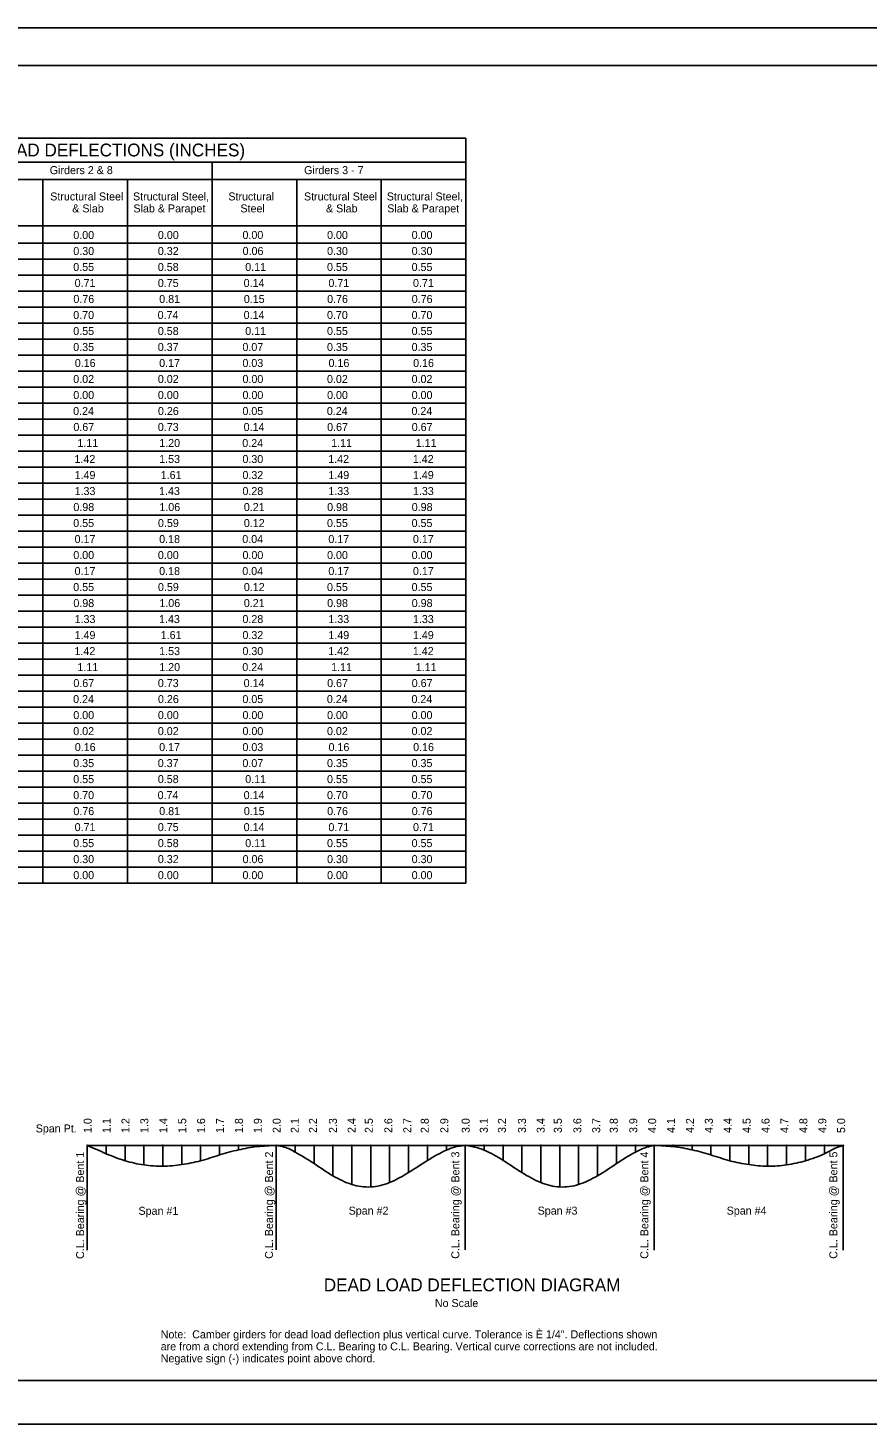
# Model space of a CAD drawing. Extents: x 208.7 to 242.8, y 328.9 to 350.7.
# Drawn here: x 217.57 to 230.69, y 328.91 to 350.71 of the extents above; entities that cross this region are included whole.
import ezdxf

# ---------------------------------------------------------------- set-up
doc = ezdxf.new("R2010")
doc.units = 0
for name, color, linetype in [('border', 7, 'Continuous'), ('Border 2660-Hwy18 - Level 62', 7, 'Continuous'), ('Dimensions', 7, 'Continuous'), ('Level 20', 7, 'Continuous'), ('Level 25', 7, 'Continuous'), ('Level 40', 7, 'Continuous'), ('Level 41', 7, 'Continuous'), ('Steel', 7, 'Continuous'), ('Text', 7, 'Continuous'), ('Title Text', 7, 'Continuous')]:
    doc.layers.add(name, color=color, linetype=linetype)

msp = doc.modelspace()

# ---------------------------------------------------------------- linework, layer by layer
at = {"layer": 'border'}
for p, q in [((210.28, 350.129), (242.291, 350.129)), ((242.291, 329.584), (210.28, 329.584))]:
    msp.add_line(p, q, dxfattribs=at)
at = {"layer": 'Border 2660-Hwy18 - Level 62'}
msp.add_lwpolyline([(208.659, 350.715), (242.778, 350.715), (242.778, 328.905), (208.659, 328.905)], close=True, dxfattribs=at)
at = {"layer": 'Dimensions'}
for centre in [(218.498, 333.259), (218.793, 333.259), (219.088, 333.259), (219.384, 333.259), (219.679, 333.259), (219.975, 333.259), (220.27, 333.259), (220.565, 333.259), (220.861, 333.259), (221.156, 333.259), (221.452, 333.259), (221.747, 333.259), (222.042, 333.259), (222.338, 333.259), (222.633, 333.259), (222.929, 333.259), (223.224, 333.259), (223.519, 333.259), (223.815, 333.259), (224.11, 333.259), (224.406, 333.259), (224.701, 333.259), (224.996, 333.259), (225.292, 333.259), (225.587, 333.259), (225.883, 333.259), (226.178, 333.259), (226.473, 333.259), (226.769, 333.259), (227.064, 333.259), (227.36, 333.259), (227.655, 333.259), (227.951, 333.259), (228.246, 333.259), (228.541, 333.259), (228.837, 333.259), (229.132, 333.259), (229.428, 333.259), (229.723, 333.259), (230.018, 333.259), (230.314, 333.259)]:
    msp.add_circle(centre, 0.004, dxfattribs=at)
at = {"layer": 'Level 20'}
for p, q in [((218.498, 331.622), (218.498, 333.259)), ((221.452, 331.626), (221.452, 333.259)), ((224.406, 331.626), (224.406, 333.259)), ((227.36, 331.774), (227.36, 333.259)), ((227.36, 331.623), (227.36, 333.259)), ((230.314, 331.774), (230.314, 333.259)), ((230.314, 331.622), (230.314, 333.259))]:
    msp.add_line(p, q, dxfattribs=at)
at = {"layer": 'Level 25'}
for p, q in [((218.498, 333.259), (221.452, 333.259)), ((224.406, 333.259), (221.452, 333.259)), ((230.314, 333.259), (224.406, 333.259))]:
    msp.add_line(p, q, dxfattribs=at)
at = {"layer": 'Level 41'}
for p, q in [((218.793, 333.259), (218.793, 333.129)), ((219.088, 333.259), (219.088, 333.019)), ((219.384, 333.259), (219.384, 332.954)), ((219.679, 333.259), (219.679, 332.934)), ((219.975, 333.259), (219.975, 332.959)), ((220.27, 333.259), (220.27, 333.019)), ((220.565, 333.259), (220.565, 333.109)), ((220.861, 333.259), (220.861, 333.189)), ((221.156, 333.259), (221.156, 333.239)), ((221.747, 333.259), (221.747, 333.154)), ((222.042, 333.259), (222.042, 332.974)), ((222.338, 333.259), (222.338, 332.784)), ((222.633, 333.259), (222.633, 332.649)), ((222.929, 333.259), (222.929, 332.609)), ((223.224, 333.259), (223.224, 332.679)), ((223.519, 333.259), (223.519, 332.834)), ((223.815, 333.259), (223.815, 333.024)), ((224.11, 333.259), (224.11, 333.184)), ((224.701, 333.259), (224.701, 333.184)), ((224.996, 333.259), (224.996, 333.024)), ((225.292, 333.259), (225.292, 332.834)), ((225.587, 333.259), (225.587, 332.679)), ((225.883, 333.259), (225.883, 332.609)), ((226.178, 333.259), (226.178, 332.649)), ((226.473, 333.259), (226.473, 332.784)), ((226.769, 333.259), (226.769, 332.974)), ((227.064, 333.259), (227.064, 333.154)), ((227.655, 333.259), (227.655, 333.239)), ((227.951, 333.259), (227.951, 333.189)), ((228.246, 333.259), (228.246, 333.109)), ((228.541, 333.259), (228.541, 333.019)), ((228.837, 333.259), (228.837, 332.959)), ((229.132, 333.259), (229.132, 332.934)), ((229.428, 333.259), (229.428, 332.954)), ((229.723, 333.259), (229.723, 333.019)), ((230.018, 333.259), (230.018, 333.129))]:
    msp.add_line(p, q, dxfattribs=at)
for points in [[(218.498, 333.259), (218.793, 333.129), (219.088, 333.019), (219.384, 332.954), (219.679, 332.934), (219.975, 332.959), (220.27, 333.019), (220.565, 333.109), (220.861, 333.189), (221.156, 333.239), (221.452, 333.259)], [(221.452, 333.259), (221.577, 333.233), (221.747, 333.154), (222.042, 332.974), (222.338, 332.784), (222.633, 332.649), (222.929, 332.609), (223.224, 332.679), (223.519, 332.834), (223.815, 333.024), (224.11, 333.184), (224.235, 333.229), (224.406, 333.259)], [(224.406, 333.259), (224.501, 333.244), (224.701, 333.184), (224.996, 333.024), (225.292, 332.834), (225.587, 332.679), (225.883, 332.609), (226.178, 332.649), (226.473, 332.784), (226.769, 332.974), (227.064, 333.154), (227.24, 333.229), (227.36, 333.259)], [(227.36, 333.259), (227.655, 333.239), (227.951, 333.189), (228.246, 333.109), (228.541, 333.019), (228.837, 332.959), (229.132, 332.934), (229.428, 332.954), (229.723, 333.019), (230.018, 333.129), (230.177, 333.21), (230.314, 333.259)]]:
    msp.add_spline(points, degree=3, dxfattribs=at)
at = {"layer": 'Steel'}
for p, q in [((224.415, 348.995), (210.932, 348.995)), ((224.415, 348.995), (224.415, 337.354)), ((224.415, 348.618), (210.932, 348.618)), ((220.449, 348.618), (220.449, 337.354)), ((224.415, 348.349), (212.517, 348.349)), ((217.805, 348.349), (217.805, 337.354)), ((219.127, 348.349), (219.127, 337.354)), ((221.771, 348.349), (221.771, 337.354)), ((223.093, 348.349), (223.093, 337.354)), ((224.415, 347.623), (210.932, 347.623)), ((224.415, 347.354), (211.725, 347.354)), ((224.415, 347.104), (211.725, 347.104)), ((224.415, 346.854), (211.725, 346.854)), ((224.415, 346.604), (211.725, 346.604)), ((224.415, 346.354), (211.725, 346.354)), ((224.415, 346.104), (211.725, 346.104)), ((224.415, 345.854), (211.725, 345.854)), ((224.415, 345.604), (211.725, 345.604)), ((224.415, 345.354), (211.725, 345.354)), ((224.415, 345.104), (211.725, 345.104)), ((224.415, 344.854), (211.725, 344.854)), ((224.415, 344.604), (211.725, 344.604)), ((224.415, 344.354), (211.725, 344.354)), ((224.415, 344.104), (211.725, 344.104)), ((224.415, 343.854), (211.725, 343.854)), ((224.415, 343.604), (211.725, 343.604)), ((224.415, 343.354), (211.725, 343.354)), ((224.415, 343.104), (211.725, 343.104)), ((224.415, 342.854), (211.725, 342.854)), ((224.415, 342.604), (211.725, 342.604)), ((224.415, 342.354), (211.725, 342.354)), ((224.415, 342.104), (211.725, 342.104)), ((224.415, 341.854), (211.725, 341.854)), ((224.415, 341.604), (211.725, 341.604)), ((224.415, 341.354), (211.725, 341.354)), ((224.415, 341.104), (211.725, 341.104)), ((224.415, 340.854), (211.725, 340.854)), ((224.415, 340.604), (211.725, 340.604)), ((224.415, 340.354), (211.725, 340.354)), ((224.415, 340.104), (211.725, 340.104)), ((224.415, 339.854), (211.725, 339.854)), ((224.415, 339.604), (211.725, 339.604)), ((224.415, 339.354), (211.725, 339.354)), ((224.415, 339.104), (211.725, 339.104)), ((224.415, 338.854), (211.725, 338.854)), ((224.415, 338.604), (211.725, 338.604)), ((224.415, 338.354), (211.725, 338.354)), ((224.415, 338.104), (211.725, 338.104)), ((224.415, 337.854), (211.725, 337.854)), ((224.415, 337.604), (211.725, 337.604)), ((224.415, 337.354), (210.932, 337.354))]:
    msp.add_line(p, q, dxfattribs=at)

# ---------------------------------------------------------------- texts
at = {"layer": 'Level 40'}
for s, height, rotation, p in [('Span Pt.', 0.125, 359.9998, (217.692, 333.461)), ('1.0', 0.125, 89.9998, (218.567, 333.452)), ('1.1', 0.125, 89.9998, (218.863, 333.452)), ('1.2', 0.125, 89.9998, (219.158, 333.452)), ('1.3', 0.125, 89.9998, (219.453, 333.452)), ('1.4', 0.125, 89.9998, (219.749, 333.452)), ('1.5', 0.125, 89.9998, (220.044, 333.452)), ('1.6', 0.125, 89.9998, (220.34, 333.452)), ('1.7', 0.125, 89.9998, (220.635, 333.452)), ('1.8', 0.125, 89.9998, (220.93, 333.452)), ('1.9', 0.125, 89.9998, (221.226, 333.452)), ('2.0', 0.125, 89.9998, (221.521, 333.452)), ('2.1', 0.125, 89.9998, (221.804, 333.452)), ('2.2', 0.125, 89.9998, (222.087, 333.452)), ('2.3', 0.125, 89.9998, (222.4, 333.452)), ('2.4', 0.125, 89.9998, (222.693, 333.452)), ('2.5', 0.125, 89.9998, (222.961, 333.452)), ('2.6', 0.125, 89.9998, (223.266, 333.452)), ('2.7', 0.125, 89.9998, (223.561, 333.452)), ('2.8', 0.125, 89.9998, (223.835, 333.452)), ('2.9', 0.125, 89.9998, (224.14, 333.452)), ('3.0', 0.125, 89.9998, (224.475, 333.452)), ('3.1', 0.125, 89.9998, (224.758, 333.452)), ('3.2', 0.125, 89.9998, (225.041, 333.452)), ('3.3', 0.125, 89.9998, (225.354, 333.452)), ('3.4', 0.125, 89.9998, (225.647, 333.452)), ('3.5', 0.125, 89.9998, (225.915, 333.452)), ('3.6', 0.125, 89.9998, (226.22, 333.452)), ('3.7', 0.125, 89.9998, (226.515, 333.452)), ('3.8', 0.125, 89.9998, (226.789, 333.452)), ('3.9', 0.125, 89.9998, (227.094, 333.452)), ('4.0', 0.125, 89.9998, (227.389, 333.452)), ('4.1', 0.125, 89.9998, (227.684, 333.452)), ('4.2', 0.125, 89.9998, (227.98, 333.452)), ('4.3', 0.125, 89.9998, (228.275, 333.452)), ('4.4', 0.125, 89.9998, (228.571, 333.452)), ('4.5', 0.125, 89.9998, (228.866, 333.452)), ('4.6', 0.125, 89.9998, (229.161, 333.452)), ('4.7', 0.125, 89.9998, (229.457, 333.452)), ('4.8', 0.125, 89.9998, (229.752, 333.452)), ('4.9', 0.125, 89.9998, (230.048, 333.452)), ('5.0', 0.125, 89.9998, (230.343, 333.452)), ('C.L. Bearing @ Bent 1', 0.12501, 89.9998, (218.448, 331.485)), ('C.L. Bearing @ Bent 2', 0.12501, 89.9998, (221.401, 331.487)), ('C.L. Bearing @ Bent 3', 0.12501, 89.9998, (224.313, 331.487)), ('C.L. Bearing @ Bent 4', 0.12501, 89.9998, (227.267, 331.487)), ('C.L. Bearing @ Bent 5', 0.12501, 89.9998, (230.221, 331.487)), ('Span #1 ', 0.125, 359.9998, (219.299, 332.174)), ('Span #2', 0.125, 359.9998, (222.583, 332.177)), ('Span #3', 0.125, 359.9998, (225.537, 332.177)), ('Span #4', 0.125, 359.9998, (228.491, 332.177))]:
    msp.add_text(s, height=height, rotation=rotation, dxfattribs=at).set_placement(p)
for s, p in [('No Scale', (223.931, 330.733)), ('Note:  Camber girders for dead load deflection plus vertical curve. Tolerance is È 1/4". Deflections shown', (219.646, 330.245)), ('are from a chord extending from C.L. Bearing to C.L. Bearing. Vertical curve corrections are not included.', (219.646, 330.057)), ('Negative sign (-) indicates point above chord.', (219.646, 329.87))]:
    msp.add_text(s, height=0.125, dxfattribs=at).set_placement(p)
at = {"layer": 'Level 41'}
msp.add_text(' DEAD LOAD DEFLECTION DIAGRAM ', height=0.2, dxfattribs=at).set_placement((222.12, 330.98))
at = {"layer": 'Text'}
for s, p in [('Girders 2 & 8', (217.912, 348.431)), ('Girders 3 - 7', (221.887, 348.431)), ('Structural Steel', (217.919, 348.02)), ('Structural Steel,', (219.213, 348.02)), ('Structural', (220.703, 348.02)), ('Structural Steel', (221.885, 348.02)), ('Structural Steel,', (223.179, 348.02)), ('& Slab', (218.263, 347.833)), ('Slab & Parapet', (219.22, 347.833)), ('Steel', (220.892, 347.833)), ('& Slab', (222.229, 347.833)), ('Slab & Parapet', (223.186, 347.833)), ('0.00', (218.28, 347.418)), ('0.00', (219.602, 347.418)), ('0.00', (220.924, 347.418)), ('0.00', (222.246, 347.418)), ('0.00', (223.568, 347.418)), ('0.30', (218.28, 347.168)), ('0.32', (219.601, 347.168)), ('0.06', (220.926, 347.168)), ('0.30', (222.246, 347.168)), ('0.30', (223.568, 347.168)), ('0.55', (218.279, 346.918)), ('0.58', (219.601, 346.918)), ('0.11', (220.967, 346.918)), ('0.55', (222.245, 346.918)), ('0.55', (223.567, 346.918)), ('0.71', (218.301, 346.668)), ('0.75', (219.601, 346.668)), ('0.14', (220.942, 346.668)), ('0.71', (222.267, 346.668)), ('0.71', (223.589, 346.668)), ('0.76', (218.281, 346.418)), ('0.81', (219.623, 346.418)), ('0.15', (220.945, 346.418)), ('0.76', (222.247, 346.418)), ('0.76', (223.569, 346.418)), ('0.70', (218.279, 346.168)), ('0.74', (219.598, 346.168)), ('0.14', (220.942, 346.168)), ('0.70', (222.245, 346.168)), ('0.70', (223.567, 346.168)), ('0.55', (218.279, 345.918)), ('0.58', (219.601, 345.918)), ('0.11', (220.967, 345.918)), ('0.55', (222.245, 345.918)), ('0.55', (223.567, 345.918)), ('0.35', (218.279, 345.668)), ('0.37', (219.6, 345.668)), ('0.07', (220.923, 345.668)), ('0.35', (222.245, 345.668)), ('0.35', (223.567, 345.668)), ('0.16', (218.303, 345.418)), ('0.17', (219.622, 345.418)), ('0.03', (220.923, 345.418)), ('0.16', (222.269, 345.418)), ('0.16', (223.591, 345.418)), ('0.02', (218.279, 345.168)), ('0.02', (219.601, 345.168)), ('0.00', (220.924, 345.168)), ('0.02', (222.245, 345.168)), ('0.02', (223.567, 345.168)), ('0.00', (218.28, 344.918)), ('0.00', (219.602, 344.918)), ('0.00', (220.924, 344.918)), ('0.00', (222.246, 344.918)), ('0.00', (223.568, 344.918)), ('0.24', (218.277, 344.668)), ('0.26', (219.603, 344.668)), ('0.05', (220.923, 344.668)), ('0.24', (222.243, 344.668)), ('0.24', (223.565, 344.668)), ('0.67', (218.281, 344.418)), ('0.73', (219.601, 344.418)), ('0.14', (220.942, 344.418)), ('0.67', (222.247, 344.418)), ('0.67', (223.569, 344.418)), ('1.11', (218.344, 344.168)), ('1.20', (219.623, 344.168)), ('0.24', (220.921, 344.168)), ('1.11', (222.31, 344.168)), ('1.11', (223.632, 344.168)), ('1.42', (218.298, 343.918)), ('1.53', (219.622, 343.918)), ('0.30', (220.923, 343.918)), ('1.42', (222.264, 343.918)), ('1.42', (223.586, 343.918)), ('1.49', (218.3, 343.668)), ('1.61', (219.646, 343.668)), ('0.32', (220.923, 343.668)), ('1.49', (222.266, 343.668)), ('1.49', (223.588, 343.668)), ('1.33', (218.3, 343.418)), ('1.43', (219.62, 343.418)), ('0.28', (220.923, 343.418)), ('1.33', (222.266, 343.418)), ('1.33', (223.588, 343.418)), ('0.98', (218.281, 343.168)), ('1.06', (219.625, 343.168)), ('0.21', (220.945, 343.168)), ('0.98', (222.247, 343.168)), ('0.98', (223.569, 343.168)), ('0.55', (218.279, 342.918)), ('0.59', (219.603, 342.918)), ('0.12', (220.945, 342.918)), ('0.55', (222.245, 342.918)), ('0.55', (223.567, 342.918)), ('0.17', (218.3, 342.668)), ('0.18', (219.622, 342.668)), ('0.04', (220.921, 342.668)), ('0.17', (222.266, 342.668)), ('0.17', (223.588, 342.668)), ('0.00', (218.28, 342.418)), ('0.00', (219.602, 342.418)), ('0.00', (220.924, 342.418)), ('0.00', (222.246, 342.418)), ('0.00', (223.568, 342.418)), ('0.17', (218.3, 342.168)), ('0.18', (219.622, 342.168)), ('0.04', (220.921, 342.168)), ('0.17', (222.266, 342.168)), ('0.17', (223.588, 342.168)), ('0.55', (218.279, 341.918)), ('0.59', (219.603, 341.918)), ('0.12', (220.945, 341.918)), ('0.55', (222.245, 341.918)), ('0.55', (223.567, 341.918)), ('0.98', (218.281, 341.668)), ('1.06', (219.625, 341.668)), ('0.21', (220.945, 341.668)), ('0.98', (222.247, 341.668)), ('0.98', (223.569, 341.668)), ('1.33', (218.3, 341.418)), ('1.43', (219.62, 341.418)), ('0.28', (220.923, 341.418)), ('1.33', (222.266, 341.418)), ('1.33', (223.588, 341.418)), ('1.49', (218.3, 341.168)), ('1.61', (219.646, 341.168)), ('0.32', (220.923, 341.168)), ('1.49', (222.266, 341.168)), ('1.49', (223.588, 341.168)), ('1.42', (218.298, 340.918)), ('1.53', (219.622, 340.918)), ('0.30', (220.923, 340.918)), ('1.42', (222.264, 340.918)), ('1.42', (223.586, 340.918)), ('1.11', (218.344, 340.668)), ('1.20', (219.623, 340.668)), ('0.24', (220.921, 340.668)), ('1.11', (222.31, 340.668)), ('1.11', (223.632, 340.668)), ('0.67', (218.281, 340.418)), ('0.73', (219.601, 340.418)), ('0.14', (220.942, 340.418)), ('0.67', (222.247, 340.418)), ('0.67', (223.569, 340.418)), ('0.24', (218.277, 340.168)), ('0.26', (219.603, 340.168)), ('0.05', (220.923, 340.168)), ('0.24', (222.243, 340.168)), ('0.24', (223.565, 340.168)), ('0.00', (218.28, 339.918)), ('0.00', (219.602, 339.918)), ('0.00', (220.924, 339.918)), ('0.00', (222.246, 339.918)), ('0.00', (223.568, 339.918)), ('0.02', (218.279, 339.668)), ('0.02', (219.601, 339.668)), ('0.00', (220.924, 339.668)), ('0.02', (222.245, 339.668)), ('0.02', (223.567, 339.668)), ('0.16', (218.303, 339.418)), ('0.17', (219.622, 339.418)), ('0.03', (220.923, 339.418)), ('0.16', (222.269, 339.418)), ('0.16', (223.591, 339.418)), ('0.35', (218.279, 339.168)), ('0.37', (219.6, 339.168)), ('0.07', (220.923, 339.168)), ('0.35', (222.245, 339.168)), ('0.35', (223.567, 339.168)), ('0.55', (218.279, 338.918)), ('0.58', (219.601, 338.918)), ('0.11', (220.967, 338.918)), ('0.55', (222.245, 338.918)), ('0.55', (223.567, 338.918)), ('0.70', (218.279, 338.668)), ('0.74', (219.598, 338.668)), ('0.14', (220.942, 338.668)), ('0.70', (222.245, 338.668)), ('0.70', (223.567, 338.668)), ('0.76', (218.281, 338.418)), ('0.81', (219.623, 338.418)), ('0.15', (220.945, 338.418)), ('0.76', (222.247, 338.418)), ('0.76', (223.569, 338.418)), ('0.71', (218.301, 338.168)), ('0.75', (219.601, 338.168)), ('0.14', (220.942, 338.168)), ('0.71', (222.267, 338.168)), ('0.71', (223.589, 338.168)), ('0.55', (218.279, 337.918)), ('0.58', (219.601, 337.918)), ('0.11', (220.967, 337.918)), ('0.55', (222.245, 337.918)), ('0.55', (223.567, 337.918)), ('0.30', (218.28, 337.668)), ('0.32', (219.601, 337.668)), ('0.06', (220.926, 337.668)), ('0.30', (222.246, 337.668)), ('0.30', (223.568, 337.668)), ('0.00', (218.28, 337.418)), ('0.00', (219.602, 337.418)), ('0.00', (220.924, 337.418)), ('0.00', (222.246, 337.418)), ('0.00', (223.568, 337.418))]:
    msp.add_text(s, height=0.125, dxfattribs=at).set_placement(p)
at = {"layer": 'Title Text'}
msp.add_text('TABLE OF DEAD LOAD DEFLECTIONS (INCHES)', height=0.2, dxfattribs=at).set_placement((214.842, 348.708))

doc.saveas('drawing.dxf')
